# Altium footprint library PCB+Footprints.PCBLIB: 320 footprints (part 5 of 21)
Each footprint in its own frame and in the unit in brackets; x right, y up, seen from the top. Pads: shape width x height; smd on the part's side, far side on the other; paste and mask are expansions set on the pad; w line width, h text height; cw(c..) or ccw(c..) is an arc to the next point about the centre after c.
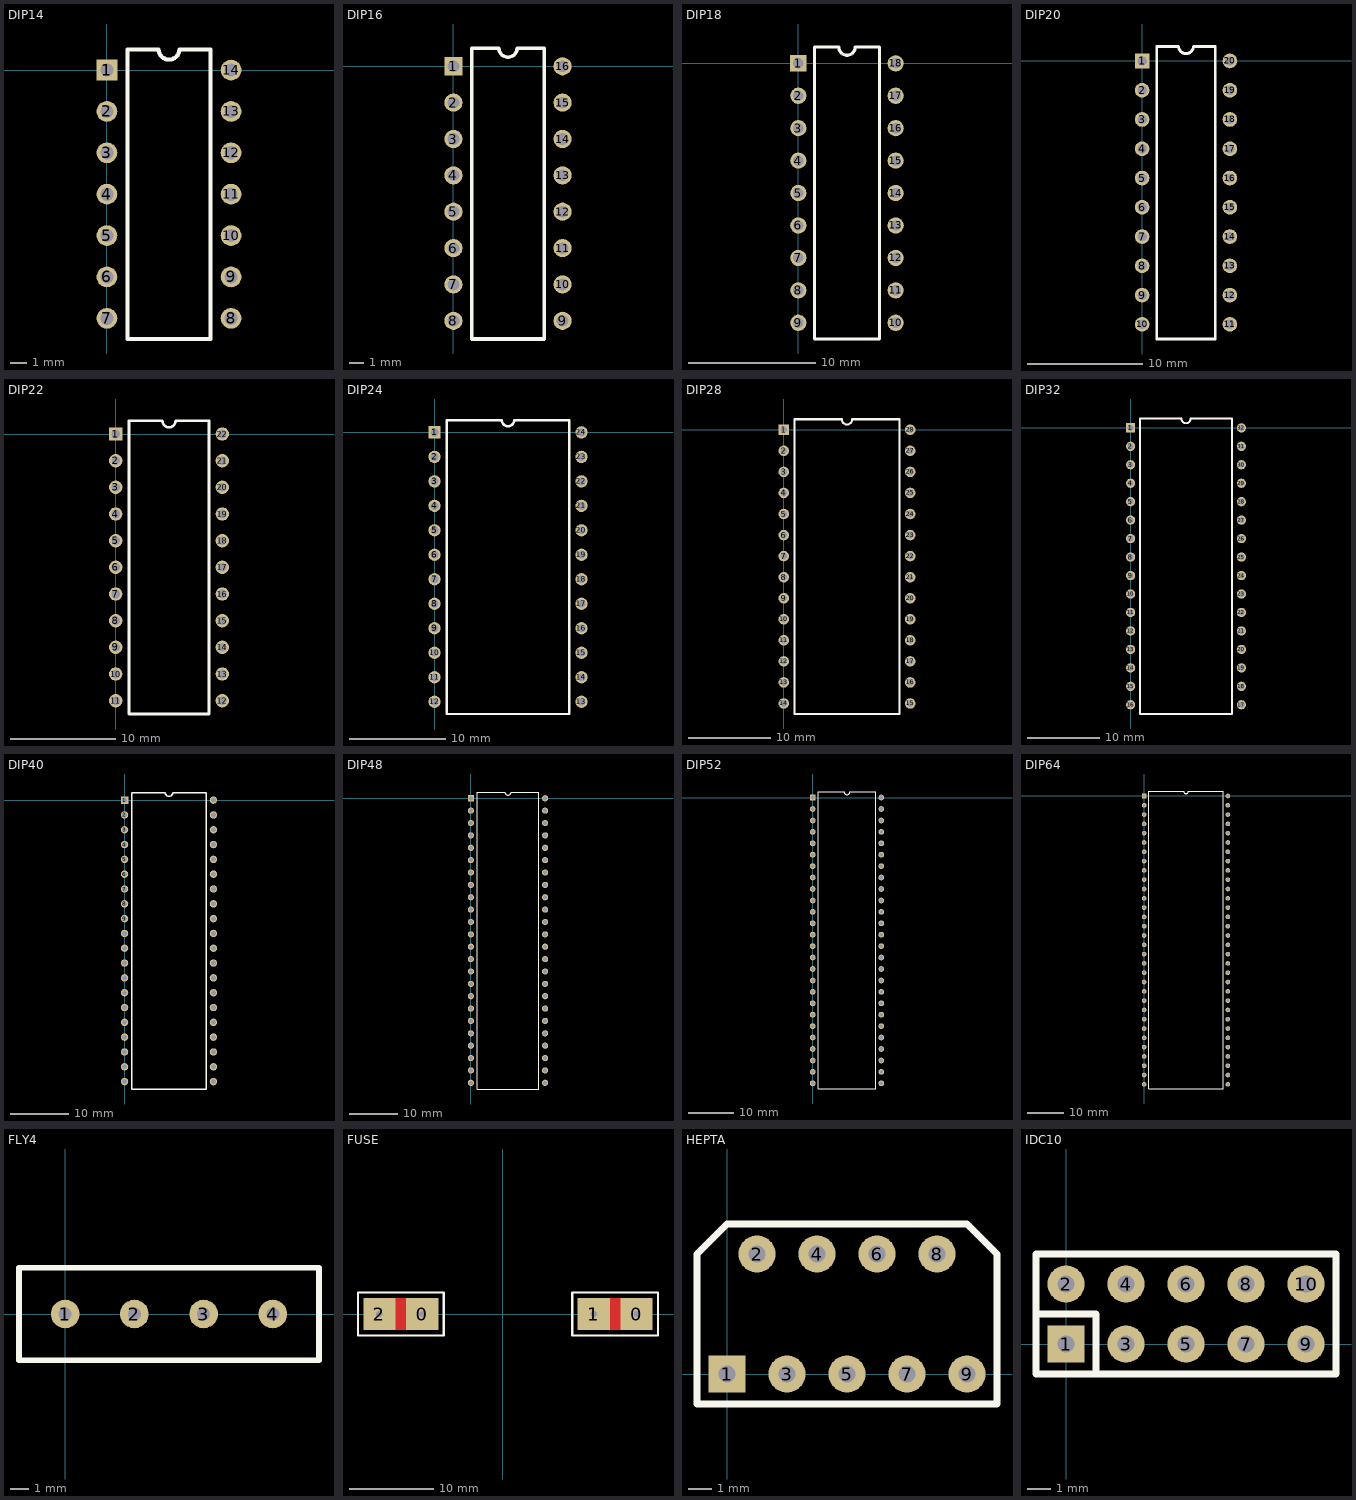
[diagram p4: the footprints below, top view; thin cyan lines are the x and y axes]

## DIP14 [mil]
pads (14):
  rect 50x50 hole 32: 1(0,0)
  round 50 hole 32: 2(0,-100) 3(0,-200) 4(0,-300) 5(0,-400) 6(0,-500) 7(0,-600) 8(300,-600) 9(300,-500) 10(300,-400) 11(300,-300) 12(300,-200) 13(300,-100) 14(300,0)
TopOverlay:
  lines w10: 50,50 50,50 ; 50,50 50,-650 250,-650 250,50 175,50 cw(c150,50) 125,50 50,50

## DIP16 [mil]
pads (16):
  rect 50x50 hole 32: 1(0,0)
  round 50 hole 32: 2(0,-100) 3(0,-200) 4(0,-300) 5(0,-400) 6(0,-500) 7(0,-600) 8(0,-700) 9(300,-700) 10(300,-600) 11(300,-500) 12(300,-400) 13(300,-300) 14(300,-200) 15(300,-100) 16(300,0)
TopOverlay:
  lines w10: 50,-750 50,50 125,50 ccw(c150,50) 175,50 250,50 250,-750 50,-750

## DIP18 [mil]
pads (18):
  rect 50x50 hole 32: 1(0,0)
  round 50 hole 32: 2(0,-100) 3(0,-200) 4(0,-300) 5(0,-400) 6(0,-500) 7(0,-600) 8(0,-700) 9(0,-800) 10(300,-800) 11(300,-700) 12(300,-600) 13(300,-500) 14(300,-400) 15(300,-300) 16(300,-200) 17(300,-100) 18(300,0)
TopOverlay:
  lines w10: 50,-850 50,50 125,50 ccw(c150,50) 175,50 250,50 250,-850 50,-850

## DIP20 [mil]
pads (20):
  rect 50x50 hole 32: 1(0,0)
  round 50 hole 32: 2(0,-100) 3(0,-200) 4(0,-300) 5(0,-400) 6(0,-500) 7(0,-600) 8(0,-700) 9(0,-800) 10(0,-900) 11(300,-900) 12(300,-800) 13(300,-700) 14(300,-600) 15(300,-500) 16(300,-400) 17(300,-300) 18(300,-200) 19(300,-100) 20(300,0)
TopOverlay:
  lines w10: 50,-950 250,-950 250,50 175,50 cw(c150,50) 125,50 50,50 50,-950

## DIP22 [mil]
pads (22):
  rect 50x50 hole 32: 1(0,0)
  round 50 hole 32: 2(0,-100) 3(0,-200) 4(0,-300) 5(0,-400) 6(0,-500) 7(0,-600) 8(0,-700) 9(0,-800) 10(0,-900) 11(0,-1000) 12(400,-1000) 13(400,-900) 14(400,-800) 15(400,-700) 16(400,-600) 17(400,-500) 18(400,-400) 19(400,-300) 20(400,-200) 21(400,-100) 22(400,0)
TopOverlay:
  lines w10: 50,-1050 50,50 175,50 ccw(c200,50) 225,50 350,50 350,-1050 50,-1050

## DIP24 [mil]
pads (24):
  rect 50x50 hole 32: 1(0,0)
  round 50 hole 32: 2(0,-100) 3(0,-200) 4(0,-300) 5(0,-400) 6(0,-500) 7(0,-600) 8(0,-700) 9(0,-800) 10(0,-900) 11(0,-1000) 12(0,-1100) 13(600,-1100) 14(600,-1000) 15(600,-900) 16(600,-800) 17(600,-700) 18(600,-600) 19(600,-500) 20(600,-400) 21(600,-300) 22(600,-200) 23(600,-100) 24(600,0)
TopOverlay:
  lines w10: 50,-1150 550,-1150 550,50 325,50 cw(c300,50) 275,50 50,50 50,-1150

## DIP28 [mil]
pads (28):
  rect 50x50 hole 32: 1(0,0)
  round 50 hole 32: 2(0,-100) 3(0,-200) 4(0,-300) 5(0,-400) 6(0,-500) 7(0,-600) 8(0,-700) 9(0,-800) 10(0,-900) 11(0,-1000) 12(0,-1100) 13(0,-1200) 14(0,-1300) 15(600,-1300) 16(600,-1200) 17(600,-1100) 18(600,-1000) 19(600,-900) 20(600,-800) 21(600,-700) 22(600,-600) 23(600,-500) 24(600,-400) 25(600,-300) 26(600,-200) 27(600,-100) 28(600,0)
TopOverlay:
  lines w10: 50,-1350 550,-1350 550,50 325,50 cw(c300,50) 275,50 50,50 50,-1350

## DIP32 [mil]
pads (32):
  rect 50x50 hole 32: 1(0,0)
  round 50 hole 32: 2(0,-100) 3(0,-200) 4(0,-300) 5(0,-400) 6(0,-500) 7(0,-600) 8(0,-700) 9(0,-800) 10(0,-900) 11(0,-1000) 12(0,-1100) 13(0,-1200) 14(0,-1300) 15(0,-1400) 16(0,-1500) 17(600,-1500) 18(600,-1400) 19(600,-1300) 20(600,-1200) 21(600,-1100) 22(600,-1000) 23(600,-900) 24(600,-800) 25(600,-700) 26(600,-600) 27(600,-500) 28(600,-400) 29(600,-300) 30(600,-200) 31(600,-100) 32(600,0)
TopOverlay:
  lines w10: 50,-1550 550,-1550 550,50 325,50 cw(c300,50) 275,50 50,50 50,-1550

## DIP40 [mil]
pads (40):
  rect 50x50 hole 32: 1(0,0)
  round 50 hole 32: 2(0,-100) 3(0,-200) 4(0,-300) 5(0,-400) 6(0,-500) 7(0,-600) 8(0,-700) 9(0,-800) 10(0,-900) 11(0,-1000) 12(0,-1100) 13(0,-1200) 14(0,-1300) 15(0,-1400) 16(0,-1500) 17(0,-1600) 18(0,-1700) 19(0,-1800) 20(0,-1900) 21(600,-1900) 22(600,-1800) 23(600,-1700) 24(600,-1600) 25(600,-1500) 26(600,-1400) 27(600,-1300) 28(600,-1200) 29(600,-1100) 30(600,-1000) 31(600,-900) 32(600,-800) 33(600,-700) 34(600,-600) 35(600,-500) 36(600,-400) 37(600,-300) 38(600,-200) 39(600,-100) 40(600,0)
TopOverlay:
  lines w10: 50,-1950 550,-1950 550,50 325,50 cw(c300,50) 275,50 50,50 50,-1950

## DIP48 [mil]
pads (48):
  rect 50x50 hole 32: 1(0,0)
  round 50 hole 32: 2(0,-100) 3(0,-200) 4(0,-300) 5(0,-400) 6(0,-500) 7(0,-600) 8(0,-700) 9(0,-800) 10(0,-900) 11(0,-1000) 12(0,-1100) 13(0,-1200) 14(0,-1300) 15(0,-1400) 16(0,-1500) 17(0,-1600) 18(0,-1700) 19(0,-1800) 20(0,-1900) 21(0,-2000) 22(0,-2100) 23(0,-2200) 24(0,-2300) 25(600,-2300) 26(600,-2200) 27(600,-2100) 28(600,-2000) 29(600,-1900) 30(600,-1800) 31(600,-1700) 32(600,-1600) 33(600,-1500) 34(600,-1400) 35(600,-1300) 36(600,-1200) 37(600,-1100) 38(600,-1000) 39(600,-900) 40(600,-800) 41(600,-700) 42(600,-600) 43(600,-500) 44(600,-400) 45(600,-300) 46(600,-200) 47(600,-100) 48(600,0)
TopOverlay:
  lines w10: 50,-2350 550,-2350 550,50 325,50 cw(c300,50) 275,50 50,50 50,-2350

## DIP52 [mil]
pads (52):
  rect 50x50 hole 32: 1(0,0)
  round 50 hole 32: 2(0,-100) 3(0,-200) 4(0,-300) 5(0,-400) 6(0,-500) 7(0,-600) 8(0,-700) 9(0,-800) 10(0,-900) 11(0,-1000) 12(0,-1100) 13(0,-1200) 14(0,-1300) 15(0,-1400) 16(0,-1500) 17(0,-1600) 18(0,-1700) 19(0,-1800) 20(0,-1900) 21(0,-2000) 22(0,-2100) 23(0,-2200) 24(0,-2300) 25(0,-2400) 26(0,-2500) 27(600,-2500) 28(600,-2400) 29(600,-2300) 30(600,-2200) 31(600,-2100) 32(600,-2000) 33(600,-1900) 34(600,-1800) 35(600,-1700) 36(600,-1600) 37(600,-1500) 38(600,-1400) 39(600,-1300) 40(600,-1200) 41(600,-1100) 42(600,-1000) 43(600,-900) 44(600,-800) 45(600,-700) 46(600,-600) 47(600,-500) 48(600,-400) 49(600,-300) 50(600,-200) 51(600,-100) 52(600,0)
TopOverlay:
  lines w10: 50,-2550 50,50 275,50 ccw(c300,50) 325,50 550,50 550,-2550 50,-2550

## DIP64 [mil]
pads (64):
  rect 50x50 hole 32: 1(0,0)
  round 50 hole 32: 2(0,-100) 3(0,-200) 4(0,-300) 5(0,-400) 6(0,-500) 7(0,-600) 8(0,-700) 9(0,-800) 10(0,-900) 11(0,-1000) 12(0,-1100) 13(0,-1200) 14(0,-1300) 15(0,-1400) 16(0,-1500) 17(0,-1600) 18(0,-1700) 19(0,-1800) 20(0,-1900) 21(0,-2000) 22(0,-2100) 23(0,-2200) 24(0,-2300) 25(0,-2400) 26(0,-2500) 27(0,-2600) 28(0,-2700) 29(0,-2800) 30(0,-2900) 31(0,-3000) 32(0,-3100) 33(900,-3100) 34(900,-3000) 35(900,-2900) 36(900,-2800) 37(900,-2700) 38(900,-2600) 39(900,-2500) 40(900,-2400) 41(900,-2300) 42(900,-2200) 43(900,-2100) 44(900,-2000) 45(900,-1900) 46(900,-1800) 47(900,-1700) 48(900,-1600) 49(900,-1500) 50(900,-1400) 51(900,-1300) 52(900,-1200) 53(900,-1100) 54(900,-1000) 55(900,-900) 56(900,-800) 57(900,-700) 58(900,-600) 59(900,-500) 60(900,-400) 61(900,-300) 62(900,-200) 63(900,-100) 64(900,0)
TopOverlay:
  lines w10: 50,-3150 50,50 425,50 ccw(c450,50) 475,50 850,50 850,-3150 50,-3150

## FLY4 [mil]
pads (4):
  round 62 hole 28: 1(0,0) 2(150,0) 3(300,0) 4(450,0)
TopOverlay:
  lines w12: -100,-100 -100,100 550,100 550,-100 -100,-100

## FUSE [mil]
pads (4):
  rect 150x150 hole 30: 0(-375,0) 0(625,0) 1(425,0) 2(-575,0)
TopLayer:
  rectangle: 475,-75 575,75
  rectangle: -525,-75 -425,75
BottomLayer:
  rectangle: 475,-75 575,75
  rectangle: -525,-75 -425,75
TopOverlay:
  lines w10: -675,-100 -675,100 -275,100 -275,-100 -675,-100 ; 325,-100 325,100 725,100 725,-100 325,-100

## HEPTA [mil]
pads (9):
  rect 62x62 hole 28: 1(0,0)
  round 62 hole 28: 2(50,200) 3(100,0) 4(150,200) 5(200,0) 6(250,200) 7(300,0) 8(350,200) 9(400,0)
TopOverlay:
  lines w12: -50,-50 -50,200 0,250 400,250 450,200 450,-50 -50,-50

## IDC10 [mil]
pads (10):
  rect 62x62 hole 28: 1(0,0)
  round 62 hole 28: 2(0,100) 3(100,0) 4(100,100) 5(200,0) 6(200,100) 7(300,0) 8(300,100) 9(400,0) 10(400,100)
TopOverlay:
  lines w12: -50,50 50,50 50,-50 ; -50,-50 450,-50 450,150 -50,150 -50,-50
